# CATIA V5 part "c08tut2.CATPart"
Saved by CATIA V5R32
Part number: Part1
Bounding box of the stored display mesh (mm): x -49.812 to 35, y -44.222 to 44.222, z 0 to 30.5
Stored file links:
  D:\PROJECTS\Project 2022\CATIA V5 6R 2022\Resources\Tutorial Files\c13_catia_v5_6r2022_tut\c13tut1\c08tut2.CATPart
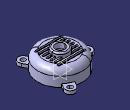
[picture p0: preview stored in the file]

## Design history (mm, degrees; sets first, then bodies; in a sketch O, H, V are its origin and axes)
Body1 (main body)
  Sketch1 on yz-plane, origin (0, 0, 0), H (0, 1, 0), V (0, 0, 1)
    line L1 (0, 0) -> (35, 0)
    line L2 (35, 0) -> (35, 15)
    line L3 (25, 25) -> (0, 25)
    line L4 (0, 25) -> (0, 0)
    arc A1 centre (25, 15) radius 10 from (25, 25) to (35, 15) cw
    axis line L5 (0, 0) -> (0, 81.873)
    radius A1 = 10
    distance L1 L3 = 25
    radius about axis L2 L5 = 35
    horizontal: L1 H, L3 H
    vertical: L2 V, L4 V, L5 V
    tangency: A1 L3, A1 L2
  Shaft1: profile Sketch1, axis Sketch1.L5, angle 360
  Shell1: ExtOffset 0, Face face of Shaft1 from Sketch1.L1, IntOffset 2.5
  Sketch2 on face of Shaft1 from Sketch1.L1, origin (0, 0, 0), H (1, 0, 0), V (0, -1, 0)
    line L1 (-34.187, 7.5) -> (-42.5, 7.5)
    arc A1 centre (-42.5, 0) radius 7.5 from (-42.5, 7.5) to (-42.5, -7.5) ccw
    point P3 (-42.5, 0)
    line L2 (-42.5, -7.5) -> (-34.187, -7.5)
    circle A2 centre (-42.5, 0) radius 3.75
    point P6 (-34.5, 0)
    point P7 (10.2014, 7.5)
    point P8 (4.3151, 7.5)
    arc A3 centre (0, 0) radius 35 from (-34.187, 7.5) to (-34.187, -7.5) ccw
    distance P3 V = 42.5
    radius A1 = 7.5
    radius A2 = 3.75
    horizontal: L1 H
    tangency: A1 L1, L2 A1
    symmetry: L1 L2 H
    coincidence: P6 H, P7 L1, P8 L1
  Pad1: profile Sketch2, direction (0, 0, 1), length 5
  CircPattern1: of Pad1, instances 3, angular step 120 {= 360.0*1 deg/CircPattern1.AngularNumber}, axis from face of Pad1
  Sketch3 on face of Shaft1 from Sketch1.L3, origin (0, 0, 25), H (1, 0, 0), V (0, 1, 0)
    construction line L1 (-20, -18) -> (20, -18)
    point P2 (20, -18)
    line L2 (-20, -16.25) -> (20, -16.25)
    line L3 (20, -19.75) -> (-20, -19.75)
    arc A1 centre (20, -18) radius 1.75 from (20, -16.25) to (20, -19.75) cw
    arc A2 centre (-20, -18) radius 1.75 from (-20, -19.75) to (-20, -16.25) cw
    distance H L1 = 18
    distance P2 V = 20
    length L1 = 40
    distance L2 L3 = 3.5
    horizontal: L1 H
    tangency: A1 L2, A2 L2, A1 L3, A2 L3
    parallelism: L1 L2
  Pocket1: profile Sketch3, direction (0, 0, -1), length 5
  RectPattern1: of Pocket1, direction 1 instances 7, spacing 6, along yz-plane
  Sketch4 on face of Shell1, origin (0, 0, 22.5), H (1, 0, 0), V (0, -1, 0)
    circle A1 centre (0, 0) radius 7.5
    circle A2 centre (0, 0) radius 12.5
    radius A2 = 12.5
    radius A1 = 7.5
  Pad2: profile Sketch4, direction (0, 0, 1), length 8
  Fillet1: radius 2, on edge [end face of Pad2 | face of Pad2 from Sketch4.A2]
  Sketch5 on face of Shaft1 from Sketch1.L3, origin (0, 0, 25), H (1, 0, 0), V (0, 1, 0)
    projected circle E1 centre (0, 0) radius 7.5 from edge [face of Pad2 from Sketch4.A1 | end face of Pad2]
  Pocket2: profile Sketch5, direction (0, 0, -1), through (limit type 6)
